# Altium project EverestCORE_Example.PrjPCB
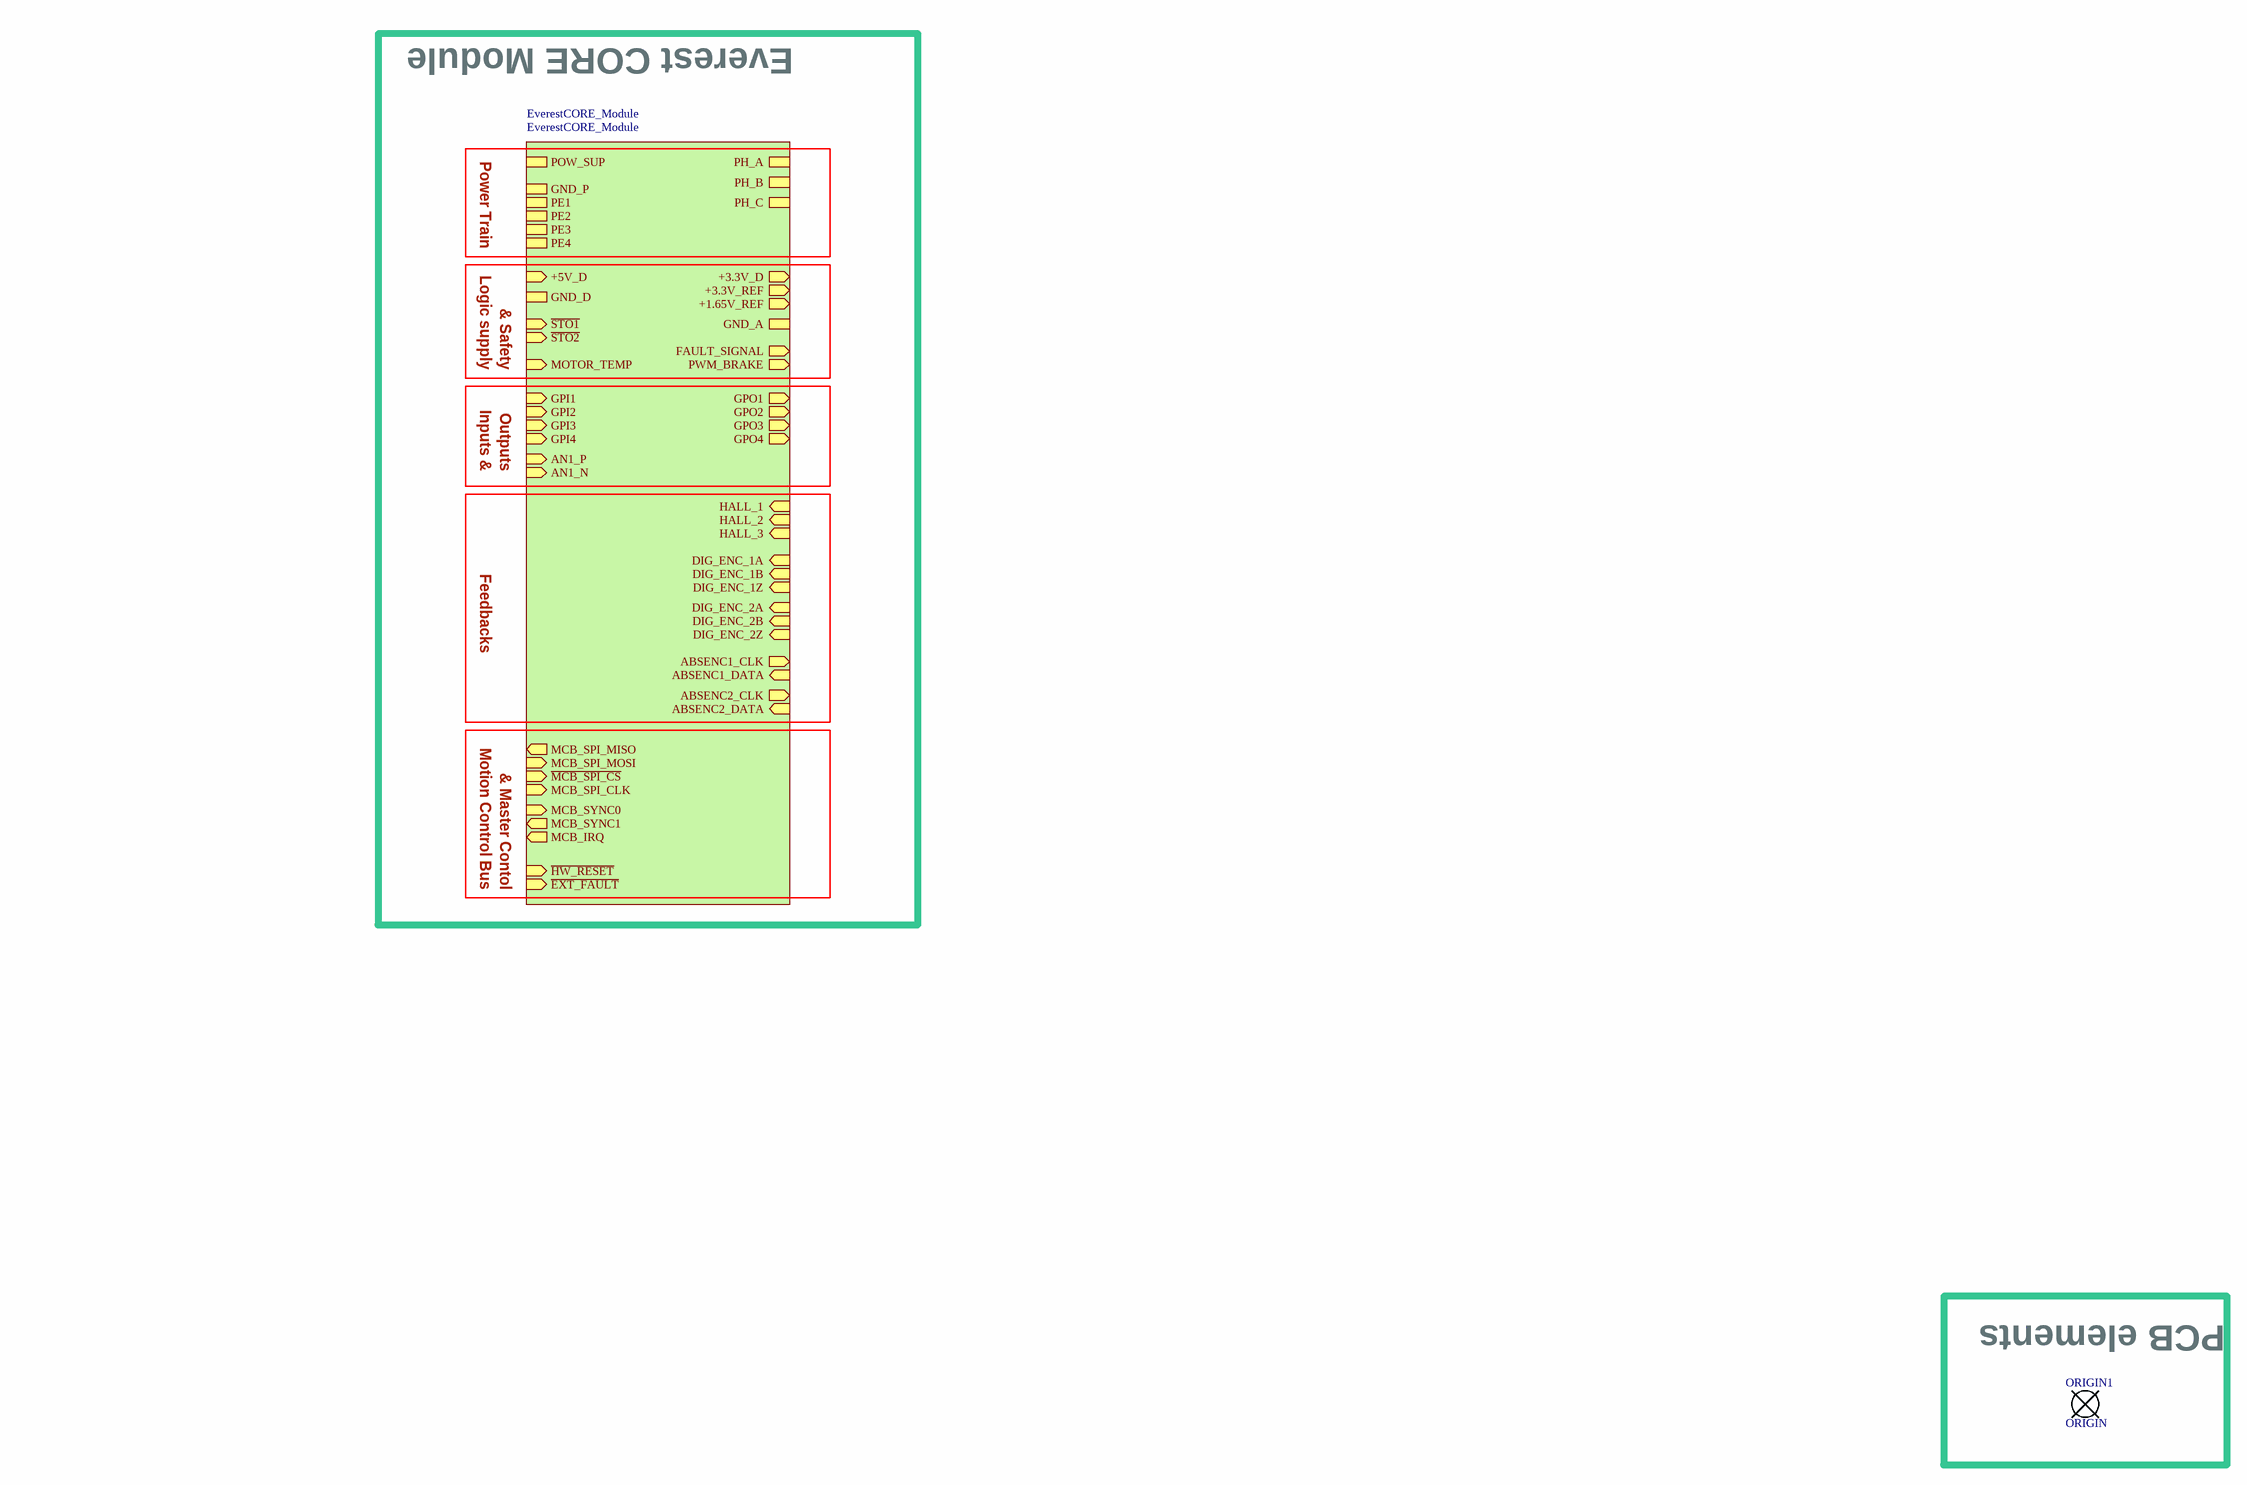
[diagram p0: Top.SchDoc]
1 sheet, 1 parts. Net scope: hierarchical (ports join the sheet entries above them; power ports are global).
Board file: EverestCORE_Example.PcbDoc

## Sheet Top.SchDoc: EVE-CORE
size A2; Organization: Ingenia Motion Control; Address1: Carrer Avila, 124, 2B; Address2: 08018 Barcelona Spain; Address3: www.ingeniamc.com; Address4: www.ingeniamc.com; Documentation: https://doc.ingeniamc.com/x/ZIPLBQ

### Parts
ORIGIN1  ORIGIN  [ORIGIN]

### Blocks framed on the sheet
PCB elements: ORIGIN1

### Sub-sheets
EverestCORE_Module = EverestCORE_Module (file not in this document): AN1_P (in), AN1_N (in), DIG_ENC_1A (in), DIG_ENC_1B (in), DIG_ENC_1Z (in), DIG_ENC_2A (in), DIG_ENC_2B (in), DIG_ENC_2Z (in), ABSENC1_CLK (out), ABSENC1_DATA (in), MOTOR_TEMP (in), HALL_1 (in), HALL_2 (in), HALL_3 (in), +3.3V_D (out), GPO4 (out), +3.3V_REF (out), +5V_D (in), GPI2 (in), ABSENC2_DATA (in), GPO1 (out), GPO3 (out), ~{STO1} (in), PWM_BRAKE (out), +1.65V_REF (out), GPI1 (in), GPI3 (in), ABSENC2_CLK (out), GPO2 (out), GPI4 (in), ~{STO2} (in), FAULT_SIGNAL (out), GND_A, GND_D, PE1, PE2, PE3, PE4, POW_SUP, GND_P, PH_C, PH_B, PH_A, MCB_SPI_CLK (in), MCB_SYNC1 (out), ~{MCB_SPI_CS} (in), MCB_SPI_MOSI (in), MCB_IRQ (out), ~{EXT_FAULT} (in), ~{HW_RESET} (in), MCB_SYNC0 (in), MCB_SPI_MISO (out)

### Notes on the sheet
- Everest CORE Module
- Power Train
- Logic supply
- & Safety
- Inputs &
- Outputs
- Feedbacks
- Motion Control Bus
- & Master Contol

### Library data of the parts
ORIGIN1 = ORIGIN: Origin of coordinate axes for pick and place; IsPreferred: True; IngeniaID: 1109; InternalStock: 0; TemperatureMaxC: 200; TemperatureMinC: -60; MTBF55h: 1E20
